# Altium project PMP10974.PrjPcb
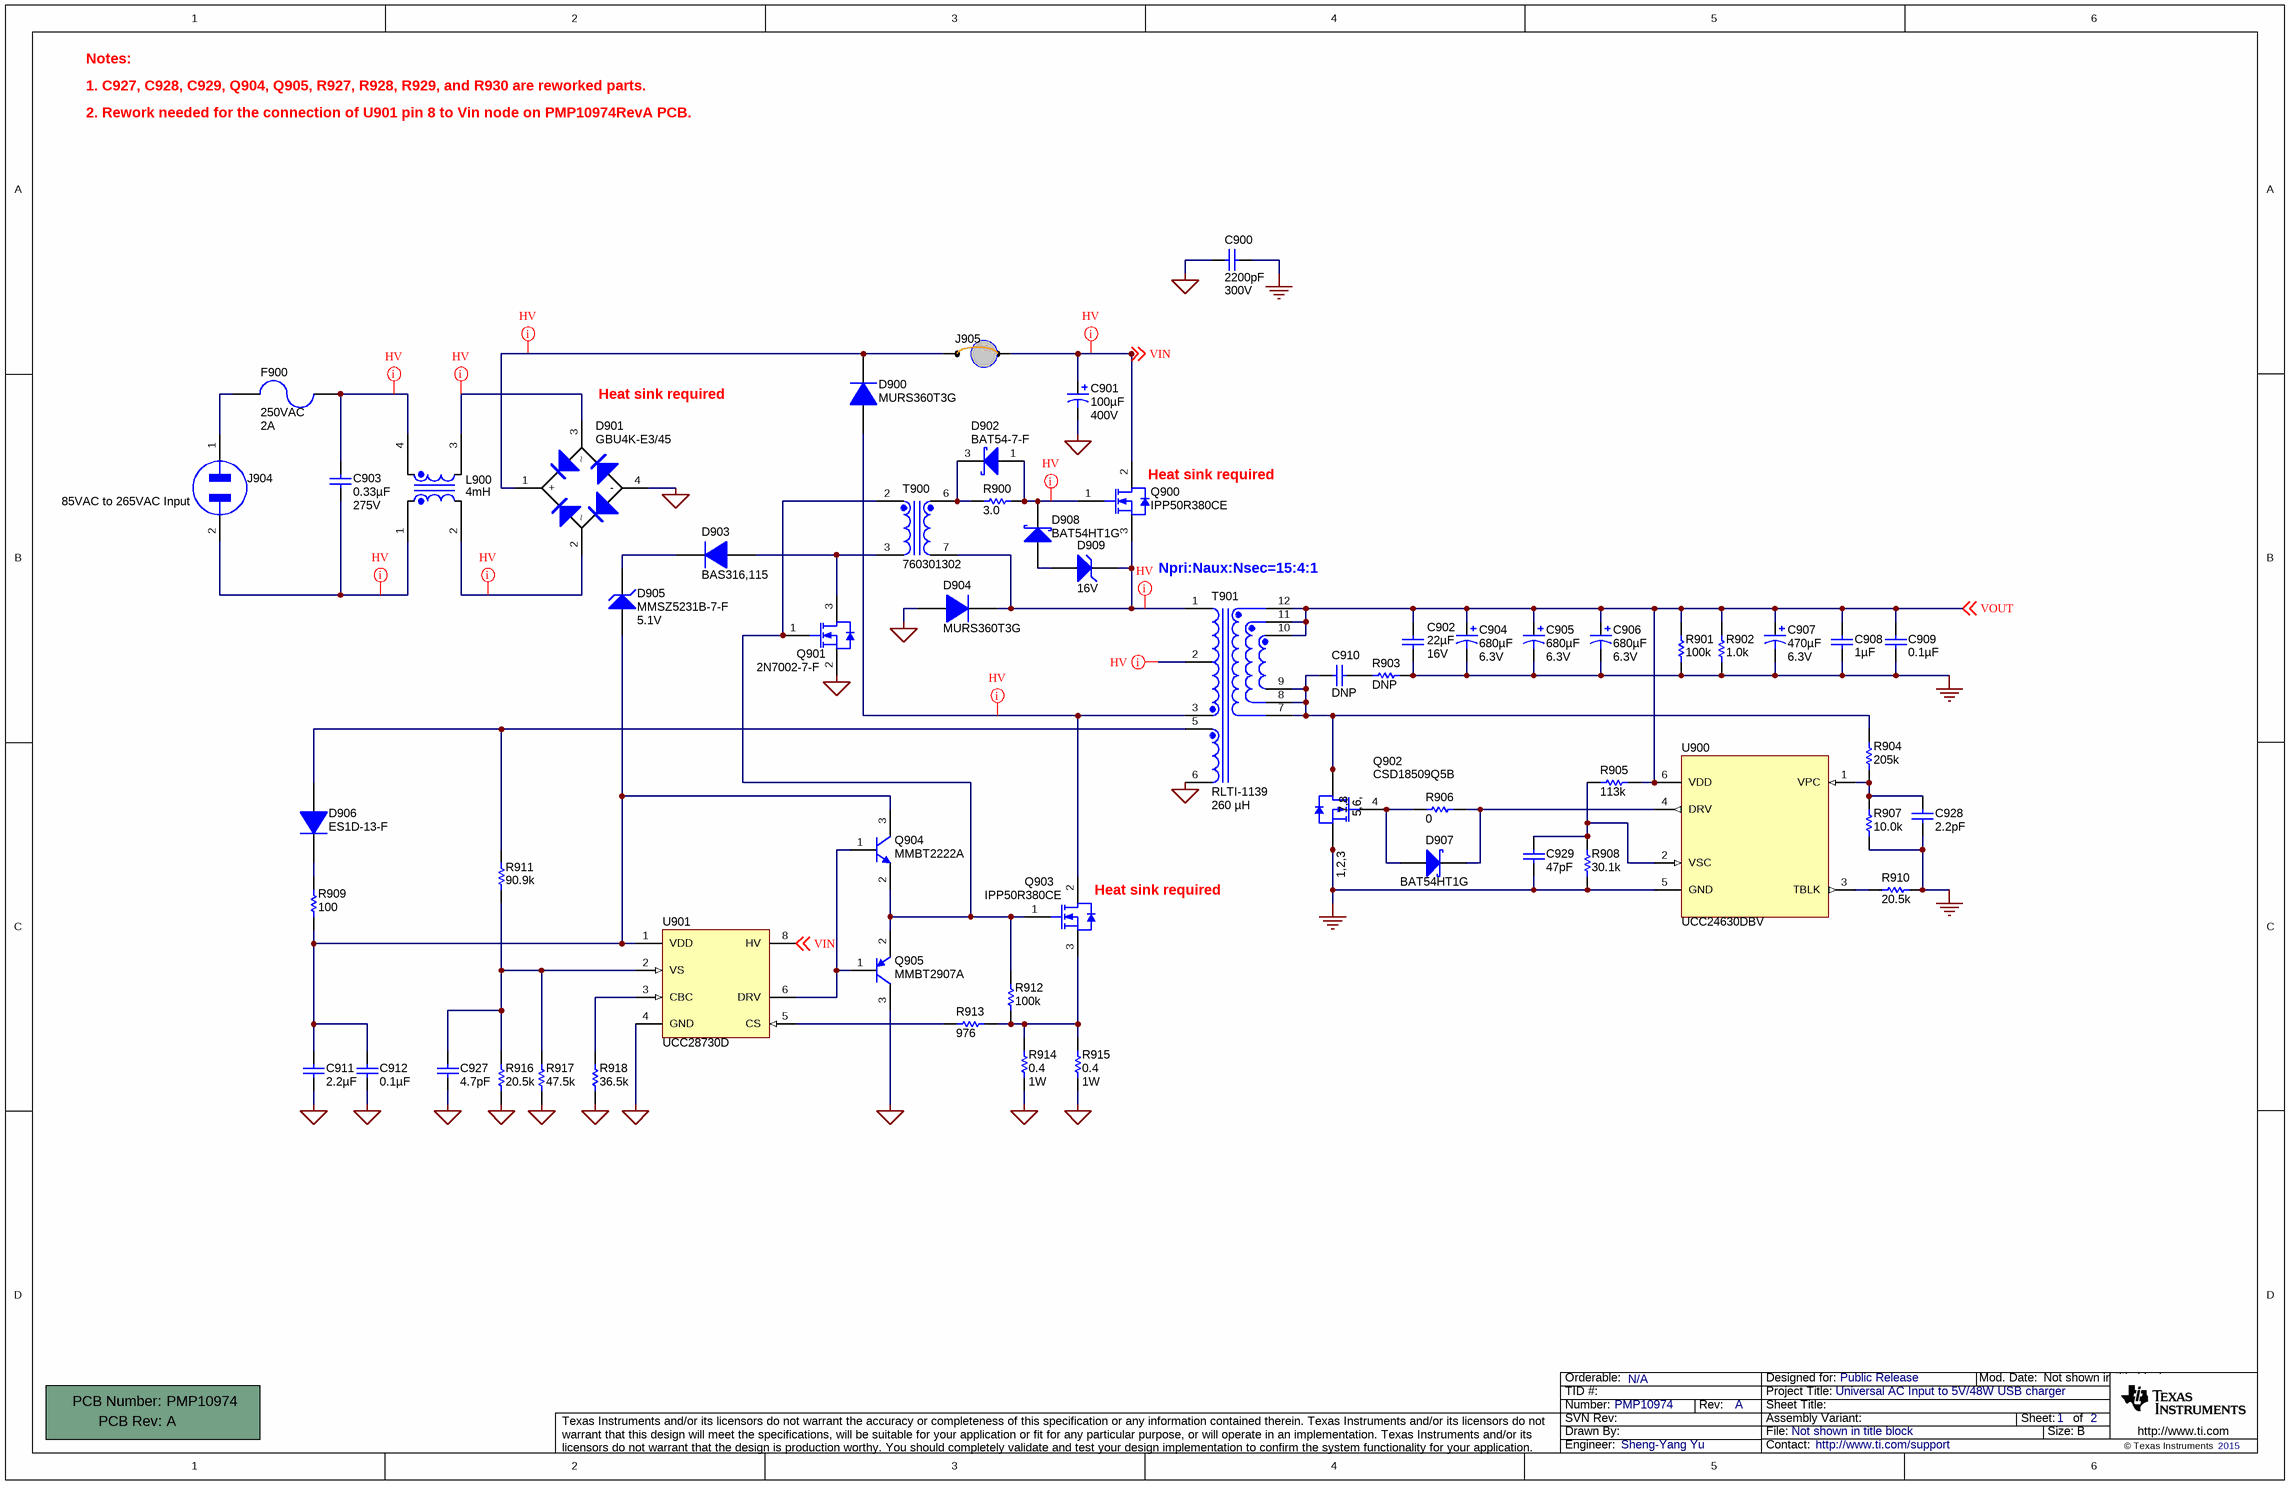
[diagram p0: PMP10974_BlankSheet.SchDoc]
CopyrightYear: 2015; EVM_Orderable: N/A; PCB_Layout: Sheng-Yang Yu; PCB_Rev: A; PRJ_Customer: Public Release; PRJ_Engineer: Sheng-Yang Yu; PRJ_Number: PMP10974; PRJ_Title: Universal AC Input to 5V/48W USB charger; SCH_Rev: A; TechSupport: http://www.ti.com/support
2 sheets, 100 parts. Net scope: global (net labels, ports and power ports of the same name join across sheets).
Board file: PMP10974_TID.PcbDoc
Sheets:
  PMP10974_BlankSheet.SchDoc
  PMP10974_TID_Hardware.SchDoc

## Sheet PMP10974_BlankSheet.SchDoc
size 431 x 279 mm; Date: Not shown in title block; ApprovedBy: Not shown in title block; CheckedBy: Not shown in title block; Author: Not shown in title block; CompanyName: Not shown in title block; Engineer: Not shown in title block; Organization: Not shown in title block; Address1: Not shown in title block; Address2: Not shown in title block; Address3: Not shown in title block; Address4: Not shown in title block; DocumentNumber: 1; Revision: Use project parameter SCH_Rev; SheetNumber: 1; SheetTotal: 2; PageSetup: Record=PageOptions¦CenterHorizontal=True¦CenterVertical=True¦PrintScale=1.00¦XCorrection=1.00¦YCorrection=1.00¦PrintKind=0¦BorderSize=5000000¦LeftOffset=0¦BottomOffset=0¦Orientation=2¦PaperLength=1000¦PaperWidth=1000¦Scale=100¦PaperSource=15¦PrintQuality=600¦MediaType=1¦DitherType=10¦PaperKind=Letter¦PrintScaleMode=1

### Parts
!PCB900  Printed Circuit Board  (value not drawn)  (mechanical)
C900  ValueDisplayed: 2200pF  Value2: 300V  [E_900x700x900]  (hidden comment: DE6E3KJ222MN3A)
C901  ValueDisplayed: 100µF  Value2: 400V  [CAPPR7.5-18X25]  (hidden comment: UPT2G101MHD6)
C902  ValueDisplayed: 22µF  Value2: 16V  [1206]  (hidden comment: 1206YD226MAT2A)
C903  ValueDisplayed: 0.33µF  Value2: 275V  [ECQUG_1500x800x1500]  (hidden comment: 890324024003)
C904  ValueDisplayed: 680µF  Value2: 6.3V  [CAPPRD500W60D1000H1250]  (hidden comment: PLE0J681MDO1)
C905  ValueDisplayed: 680µF  Value2: 6.3V  [CAPPRD500W60D1000H1250]  (hidden comment: PLE0J681MDO1)
C906  ValueDisplayed: 680µF  Value2: 6.3V  [CAPPRD500W60D1000H1250]  (hidden comment: PLE0J681MDO1)
C907  ValueDisplayed: 470µF  Value2: 6.3V  [SEPC_C55]  (hidden comment: 6.3YXJ470M6.3X11)
C908  ValueDisplayed: 1µF  [0603]  (hidden comment: C0603C105K4PACTU)
C909  ValueDisplayed: 0.1µF  [0805_HV]  (hidden comment: 08053C104KAT2A)
C910  ValueDisplayed: DNP  [0603]  (hidden comment: C1608C0G2A101J)
C911  ValueDisplayed: 2.2µF  [1206]  (hidden comment: GRM316R61E225KA12D)
C912  ValueDisplayed: 0.1µF  [0603]  (hidden comment: 06035C104KAT2A)
C927  ValueDisplayed: 4.7pF  [0603]  (hidden comment: 06035A4R7CAT2A)
C928  ValueDisplayed: 2.2pF  [0603]  (hidden comment: 06035A2R2CAT2A)
C929  ValueDisplayed: 47pF  [0603]  (hidden comment: 06035A470JAT2A)
D900  MURS360T3G  [SMC]
D901  GBU4K-E3/45  [GBU]
D902  BAT54-7-F  [SOT-23]
D903  BAS316,115  [sod-323]
D904  MURS360T3G  [SMC]
D905  MMSZ5231B-7-F  value 5.1V  [SOD-123]
D906  ES1D-13-F  [SMA]
D907  BAT54HT1G  [sod-323]
D908  BAT54HT1G  [sod-323]
D909  value 16V  [sod-323]  (hidden comment: MMSZ5246BS-7-F)
F900  VAC_V: 250VAC  Irating_A: 2A  [Fuse_RST]  (hidden comment: RST 2-BULK)
J904  770W-X2/10  [CONN_AC_770W-SERIES]  (value not drawn)
J905  923345-03-C  [923345-03-C]  (value not drawn)
L900  ValueDisplayed: 4mH  [WE-CMB_XS]  (hidden comment: 744821240)
Q900  IPP50R380CE  [TO-220AB]
Q901  2N7002-7-F  [SOT-23]
Q902  CSD18509Q5B  [TRANS_NexFET_Q5B]
Q903  IPP50R380CE  [TO-220AB]
Q904  MMBT2222A  [SOT-23]
Q905  MMBT2907A  [SOT-23]
R900  ValueDisplayed: 3.0  [0603]  (hidden comment: CRCW06033R00JNEA)
R901  ValueDisplayed: 100k  [0603]  (hidden comment: CRCW0603100KJNEA)
R902  ValueDisplayed: 1.0k  [0603]  (hidden comment: CRCW06031K00JNEA)
R903  value DNP  [0805_HV]  (hidden comment: CRCW08050000Z0EA)
R904  ValueDisplayed: 205k  [0603]  (hidden comment: CRCW0603205KFKEA)
R905  ValueDisplayed: 113k  [0603]  (hidden comment: CRCW0603113KFKEA)
R906  ValueDisplayed: 0  [0603]  (hidden comment: CRCW06030000Z0EA)
R907  ValueDisplayed: 10.0k  [0603]  (hidden comment: CRCW060310K0FKEA)
R908  ValueDisplayed: 30.1k  [0603]  (hidden comment: CRCW060330K1FKEA)
R909  ValueDisplayed: 100  [0603]  (hidden comment: CRCW0603100RFKEA)
R910  ValueDisplayed: 20.5k  [0603]  (hidden comment: CRCW060320K5FKEA)
R911  ValueDisplayed: 90.9k  [0603]  (hidden comment: CRCW060390K9FKEA)
R912  value 100k  [0805_HV]  (hidden comment: CRCW0805100KJNEA)
R913  ValueDisplayed: 976  [0603]  (hidden comment: CRCW0603976RFKEA)
R914  ValueDisplayed: 0.4  Value2: 1W  [2010]  (hidden comment: CSRN2010FKR400)
R915  ValueDisplayed: 0.4  Value2: 1W  [2010]  (hidden comment: CSRN2010FKR400)
R916  ValueDisplayed: 20.5k  [0603]  (hidden comment: CRCW060320K5FKEA)
R917  ValueDisplayed: 47.5k  [0603]  (hidden comment: CRCW060347K5FKEA)
R918  ValueDisplayed: 36.5k  [0603]  (hidden comment: CRCW060336K5FKEA)
T900  760301302  [Wurth_760301302]
T901  RLTI-1139  value 260 µH  [Renco_RLTI-1132]
U900  UCC24630DBV  [DBV0006A_N]
U901  UCC28730D  [D0007A_N]

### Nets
GND: C900.2 C901.2(-) C911.2 C912.2 C927.2 D901.4(-) D904.2(A) Q901.2(S) Q905.3(C) R914.1 R915.1 R916.1 R917.1 R918.1 T901.6 U901.4(GND)
GND2: C900.1 C902.2 C904.2(-) C905.2(-) C906.2(-) C907.2(-) C908.2 C909.2 C928.2 C929.2 Q902.1(S) Q902.2(S) Q902.3(S) R901.1 R902.1 R903.2 R907.1 R908.1 R910.1 U900.5(GND)
VIN: C901.1(+) J905.2 Q900.2(D) U901.8(HV) ; off-sheet VIN
VOUT: C902.1 C904.1(+) C905.1(+) C906.1(+) C907.1(+) C908.1 C909.1 R901.2 R902.2 R905.2 T901.10(5V) T901.11(5V) T901.12(5V) U900.6(VDD) ; off-sheet VOUT
NetC903_1: C903.1 F900.1 L900.4
NetC903_2: C903.2 J904.2(Hot) L900.1
NetC910_1: C910.1 R903.1
NetC910_2: C910.2 Q902.5(D) Q902.6(D) Q902.7(D) Q902.8(D) R904.2 T901.7(RET) T901.8(RET) T901.9(RET)
NetC911_1: C911.1 C912.1 D905.2(A) Q904.3(C) R909.1 U901.1(VDD)
NetC927_1: C927.1 R911.1 R916.2 R917.2 U901.2(VS)
NetC928_1: C928.1 R904.1 R907.2 U900.1(VPC)
NetC929_1: C929.1 R905.1 R908.2 U900.2(VSC)
NetD900_1: D900.1(K) D901.1(+) J905.1
NetD900_2: D900.2(A) Q903.2(D) T901.3(DRAIN)
NetD901_2: D901.2 L900.2
NetD901_3: D901.3 L900.3
NetD902_1: D902.1(A) D908.1(K) Q900.1(G) R900.2
NetD902_3: D902.3(K) R900.1 T900.6
NetD903_1: D903.1(K) D905.1(K)
NetD903_2: D903.2(A) Q901.3(D) T900.3
NetD904_1: D904.1(K) D909.1(K) Q900.3(S) T900.7 T901.1(VDC+)
NetD906_1: D906.1(K) R909.2
NetD906_2: D906.2(A) R911.2 T901.5
NetD907_1: D907.1(K) R906.2 U900.4(DRV)
NetD907_2: D907.2(A) Q902.4(G) R906.1
NetD908_2: D908.2(A) D909.2(A)
NetF900_2: F900.2 J904.1(Neutral)
NetQ901_1: Q901.1(G) Q903.1(G) Q904.2(E) Q905.2(E) R912.2 T900.2
NetQ903_3: Q903.3(S) R912.1 R913.2 R914.2 R915.2
NetQ904_1: Q904.1(B) Q905.1(B) U901.6(DRV)
NetR910_2: R910.2 U900.3(TBLK)
NetR913_1: R913.1 U901.5(CS)
NetR918_2: R918.2 U901.3(CBC)

Not connected (* = marked no-connect by the designer): T901 2

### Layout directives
net class HV: NetC903_1, NetC903_2, NetD900_1, NetD900_2, NetD901_2, NetD901_3, NetD902_1, NetD904_1, NetT901_2, VIN

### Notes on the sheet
- Notes:
- 1. C927, C928, C929, Q904, Q905, R927, R928, R929, and R930 are reworked parts.
- 2. Rework needed for the connection of U901 pin 8 to Vin node on PMP10974RevA PCB.
- (near D901) Heat sink required
- (near J904) 85VAC to 265VAC Input
- (near Q900) Heat sink required
- (near T901) Npri:Naux:Nsec=15:4:1
- (near Q903) Heat sink required

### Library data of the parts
!PCB900 = PCB: Manufacturer: Any; PartNumber: PMP10974; SymbolCreator: a0412235
C900 = DE6E3KJ222MN3A: CAP, CERM, 2200 pF, 300 V, +/- 20%, E, TH, 2- Leads, Body 9x7mm, Pin Spacing 7.5mm; Manufacturer: MuRata; Polarized: N; CompType: Capacitor; Value: 2200pF; U/M: EA; Cap_F: 0.0000000022; Tolerance_%: 20; Value1: Unknown; VDC_V: 300; TaMin_C: -40; TaMax_C: 125; Cap_Case: 9x7x9mm
C901 = EEUED2W330S: CAP ALUM 100UF 400V 20% RADIAL; Manufacturer: Panasonic; Polarized: Y; CompType: Capacitor; U/M: EA; Cap_F: 0.000033; Tolerance_%: 20; Value1: 0.868117 ohm; VDC_V: 450; ESR_ohm: 0.868117; IRMS_A: 0.85; TaMin_C: -25; TaMax_C: 105; AC_Derating: 0.3
C902 = 1206YD226MAT2A: CAP, CERM, 22 µF, 16 V, +/- 20%, X5R, 1206; Manufacturer: AVX; Polarized: N; CompType: Capacitor; Value: 22uF; U/M: EA; Cap_F: 0.000022; Tolerance_%: 20; Value1: Unknown; VDC_V: 16; TaMin_C: -55; TaMax_C: 85
C903 = ECQ-U3A104MG: CAP FILM 0.33UF 10% 275V RADIAL; Manufacturer: Wurth; Polarized: N; CompType: Capacitor; U/M: EA; Cap_F: 0.0000001; Tolerance_%: 20; Value1: Unknown; VDC_V: 275; TaMin_C: -40; TaMax_C: 100; Cap_Case: 15x8x15mm
C904-C906 = UVY2G4R7MPD: CAP ALUM 680UF 6.3V 20% RADIAL; Manufacturer: Nichicon; Polarized: Y; CompType: Capacitor; U/M: EA; Cap_F: 0.0000047; Tolerance_%: 20; Value1: Unknown; VDC_V: 6.3; TaMin_C: -40; TaMax_C: 105; Cap_Case: 10x12.5
C907 = 6SEPC220M: CAP ALUM 470UF 6.3V 20% RADIAL; Manufacturer: Rubycon; Polarized: Y; CompType: Capacitor; U/M: EA; Cap_F: 0.00022; Tolerance_%: 20; Value1: 0.018 ohm; VDC_V: 6.3; ESR_ohm: 0.018; IRMS_A: 2.98; TaMin_C: -55; TaMax_C: 105; Cap_Case: 6.3x5.5
C908 = C0603C105K4PACTU: CAP, CERM, 1 µF, 16 V, +/- 10%, X5R, 0603; Manufacturer: Kemet; Polarized: N; CompType: Capacitor; Value: 1uF; U/M: EA; Cap_F: 0.000001; Tolerance_%: 10; Value1: Unknown; VDC_V: 16; Value2: 16V; TaMin_C: -55; TaMax_C: 85
C909 = 08053C104KAT2A: CAP, CERM, 0.1uF, 25V, +/-10%, X7R, 0805; Manufacturer: AVX; Polarized: N; CompType: Capacitor; U/M: EA; Cap_F: 0.0000001; Tolerance_%: 10; ESR_Ohm: 0.28; Value1: 0.28 ohm; VDC_V: 25; TaMin_C: -55; TaMax_C: 125; Cap_Case: 0805
C910 = C1608C0G2A101J: CAP, CERM, 100pF, 100V, +/-5%, C0G/NP0, 0603; Manufacturer: TDK; Polarized: N; CompType: Capacitor; U/M: EA; Cap_F: 0.0000000001; Tolerance_%: 5; ESR_Ohm: 0.1202; Value1: 0.1202 ohm; VDC_V: 100; TaMin_C: -55; TaMax_C: 125
C911 = GRM316R61E225KA12D: CAP, CERM, 2.2 µF, 25 V, +/- 10%, X5R, 1206; Manufacturer: MuRata; Polarized: N; CompType: Capacitor; Value: 2.2uF; U/M: EA; Cap_F: 0.0000022; Tolerance_%: 10; ESR_ohm: 0.006; Value1: 0.006 ohm; VDC_V: 25; Value2: 25V; TaMin_C: -55; TaMax_C: 85
C912 = 06035C104KAT2A: CAP, CERM, 0.1uF, 50V, +/-10%, X7R, 0603; Manufacturer: AVX; Polarized: N; CompType: Capacitor; U/M: EA; Cap_F: 0.0000001; Tolerance_%: 10; Value1: Unknown; VDC_V: 50; TaMin_C: -55; TaMax_C: 125
C927 = 06035A4R7CAT2A: CAP, CERM, 4.7 pF, 50 V, +/- 5%, C0G/NP0, 0603; Manufacturer: AVX; Polarized: N; CompType: Capacitor; Value: 4.7pF; U/M: EA; Cap_F: 0.0000000000047; Tolerance_%: 5; ESR_ohm: 0.633; Value1: 0.633 ohm; VDC_V: 50; Value2: 50V; TaMin_C: -55; TaMax_C: 125
C928 = 06035A2R2CAT2A: CAP, CERM, 2.2 pF, 50 V, +/- 11%, C0G/NP0, 0603; Manufacturer: AVX; Polarized: N; CompType: Capacitor; Value: 2.2pF; U/M: EA; Cap_F: 0.0000000000022; Tolerance_%: 11; ESR_ohm: 1.033; Value1: 1.033 ohm; VDC_V: 50; Value2: 50V; TaMin_C: -55; TaMax_C: 125
C929 = 06035A470JAT2A: CAP, CERM, 47 pF, 50 V, +/- 5%, C0G/NP0, 0603; Manufacturer: AVX; Polarized: N; CompType: Capacitor; Value: 47pF; U/M: EA; Cap_F: 0.000000000047; Tolerance_%: 5; ESR_ohm: 0.174; Value1: 0.174 ohm; VDC_V: 50; Value2: 50V; TaMin_C: -55; TaMax_C: 125
D900 D904 = MURS360T3G: Diode, Ultrafast, 600 V, 3 A, SMC; Manufacturer: ON Semiconductor; U/M: EA; Vf_V: 1.25; Value: 600V; Value1: 3A; Value2: 1.25V; Io_A: 3; Vr_V: 600; TJmax_C: 175; RJC_CperW: 11
D901 = GBU4K-E3/45: Diode, Switching-Bridge, 800V, 4A, TH; Manufacturer: Vishay-Semiconductor; U/M: EA; Vf_V: 1; Value2: 1V; Io_A: 4; Vr_V: 800; TJmax_C: 150; RJC_CperW: 4.2
D902 = BAT54-7-F: Diode, Schottky, 30 V, 0.2 A, SOT-23; Manufacturer: Diodes Inc.; U/M: EA; Vf_V: 0.65; Value: 30V; Value1: 0.2A; Value2: 0.65V; Io_A: 0.2; Vr_V: 30; TJmax_C: 125
D903 = BAS316,115: Diode, Ultrafast, 100 V, 0.25 A, SOD-323; Manufacturer: NXP Semiconductor; U/M: EA; Vf_V: 1.4; Value: 100V; Value1: 0.25A; Value2: 1.4V; Io_A: 0.25; Vr_V: 100; TJmax_C: 150
D905 = MMSZ5231B-7-F: Diode, Zener, 5.1 V, 500 mW, SOD-123; Manufacturer: Diodes Inc.; SymbolCreator: a0412235; U/M: EA; Power_W: 0.5; Vz_V: 5.1; Value1: 0.5W; RJA_CperW: 350
D906 = ES1D-13-F: Diode, Ultrafast, 200V, 1A, SMA; Manufacturer: Diodes Inc.; U/M: EA; Vf_V: 0.92; Value2: 0.92V; Io_A: 1; Vr_V: 200; TJmax_C: 150; RJC_CperW: 25
D907 D908 = BAT54HT1G: Diode, Schottky, 30V, 0.2A, SOD-323; Manufacturer: ON Semiconductor; U/M: EA; Vf_V: 0.35; Value2: 0.35V; Io_A: 0.2; Vr_V: 30
D909 = MMSZ5246BS-7-F: Diode, Zener, 16 V, 200 mW, SOD-323; Manufacturer: Diodes Inc.; SymbolCreator: a0412235; U/M: EA; Power_W: 0.2; Vz_V: 16; Value1: 0.2W; RJA_CperW: 350
F900 = RST 500: FUSE BOARD MOUNT 2A 250VAC RAD; Manufacturer: Bel Fuse; U/M: EA; OpeningTime_100%_min: 1; OpeningTime_200%_max: 120; VDC_V: 250; Rtyp_Ohm: 0.18; MeltingTyp: 1.7; Vdrop: 0.114; Soldering_Wave_MaxTemp_C: 260; Soldering_Wave_MaxTime_s: 10
J904 = 770W-X2/10: AC Receptacle, 2.5A, R/A, TH; Manufacturer: Qualtek Electronics Corporation; SymbolCreator: a0412235; U/M: EA
J905 = 923345-03-C: Jumper Wire, 300mil spacing, Orange, pkg of 200; Manufacturer: 3M; SymbolCreator: a0412235; U/M: EA
L900 = 744821240: Coupled inductor, 4 mH, 1.5 A, 0.14 ohm, +/- 30%, TH; Manufacturer: Wurth Elektronik eiSos; SymbolCreator: a0412235; Ind_H: 4.0E-3; DCR_ohm: 0.14; Isat: 1.5; Tolerance_%: 30; Value: 4mH
Q900 Q903 = IPP50R199CP: MOSFET N CH 500V 9.9A PGTO220; Manufacturer: Infineon Technologies; Alternate Manufacturer: None; U/M: EA; Value: 550V; VdsMax_V: 550; Value1: ? ohm; Rdson45_ohm: 0; Value2: 34 nC; QgTyp_nC: 34; Vgs_V: 20
Q901 = 2N7002-7-F: MOSFET, N-CH, 60 V, 0.17 A, SOT-23; Manufacturer: Diodes Inc.; Alternate Manufacturer: None; U/M: EA; ChType: N; Value: 60V; VdsMax_V: 60; Value1: 7.5 ohm; Rdson45_ohm: 7.5; Value2: 223 nC; QgTyp_nC: 223; Vgs_V: 20; IdsMax_A: 0.17
Q902 = CSD18509Q5B: MOSFET, N-CH, 40 V, 38 A, SON 5x6mm; Manufacturer: Texas Instruments; Alternate Manufacturer: None; U/M: EA; ChType: N; Value: 40V; VdsMax_V: 40; Value1: 0.0017 ohm; Rdson45_ohm: 0.0017; Value2: 150 nC; QgTyp_nC: 150; Vgs_V: 20; IdsMax_A: 38
Q904 = MMBT2222A, Fairchild Semiconductor: Transistor, NPN, 40 V, 0.15 A, SOT-23; CompType: BJT; PNP: 0; NPN: 1; Vceo_V: 40; Vcesat1_V: 0.3; Value: 40 V; IcRated_A: 0.15; Value1: 0.15 A; HfeMax: 300; TaMin_C: -55; TaMax_C: 150; U/M: EA
Q905 = MMBT2907A, Fairchild Semiconductor: Transistor, PNP, 60 V, 0.8 A, SOT-23; CompType: BJT; PNP: 1; NPN: 0; Vceo_V: 60; Vcesat1_V: 1.6; Value: 60 V; IcRated_A: 0.8; Value1: 0.8 A; HfeMax: 300; TaMin_C: -55; TaMax_C: 150; U/M: EA
R900 = CRCW06033R00JNEA: RES, 3.0, 5%, 0.1 W, 0603; Manufacturer: Vishay-Dale; CompType: Resistor; Value: 3.0; Res_ohm: 3; Value_Code: 3R00; Tolerance_%: 5; Power_W: 0.1; Value2: 0.1W; VDC_V: 75; TempCo: 200 ppm/C; EIA_Code: E24; U/M: EA
R901 = CRCW0603100KJNEA: RES, 100 k, 5%, 0.1 W, 0603; Manufacturer: Vishay-Dale; CompType: Resistor; Value: 100k; Res_ohm: 100000; Tolerance_%: 5; Power_W: 0.1; Value2: 0.1W; VDC_V: 75; TempCo: 200 ppm/C; EIA_Code: E24; U/M: EA
R902 = CRCW06031K00JNEA: RES, 1.0 k, 5%, 0.1 W, 0603; Manufacturer: Vishay-Dale; CompType: Resistor; Value: 1.0k; Res_ohm: 1000; Value_Code: 1k00; Tolerance_%: 5; Power_W: 0.1; Value2: 0.1W; VDC_V: 75; TempCo: 200 ppm/C; EIA_Code: E24; U/M: EA
R903 = CRCW08050000Z0EA: RES, 0 ohm, 5%, 0.125W, 0805; Manufacturer: Vishay-Dale; CompType: Resistor; Res_ohm: 0; Value_Code: 0000; Tolerance_%: 5; Power_W: 0.125; VDC_V: 150; TempCo: 200 ppm/C; EIA_Code: E24; U/M: EA
R904 = CRCW0603205KFKEA: RES, 205 k, 1%, 0.1 W, 0603; Manufacturer: Vishay-Dale; CompType: Resistor; Value: 205k; Res_ohm: 205000; Tolerance_%: 1; Power_W: 0.1; Value2: 0.1W; VDC_V: 75; TempCo: 100 ppm/C; EIA_Code: E96; U/M: EA
R905 = CRCW0603113KFKEA: RES, 113 k, 1%, 0.1 W, 0603; Manufacturer: Vishay-Dale; CompType: Resistor; Value: 113k; Res_ohm: 113000; Tolerance_%: 1; Power_W: 0.1; Value2: 0.1W; VDC_V: 75; TempCo: 100 ppm/C; EIA_Code: E96; U/M: EA
R906 = CRCW06030000Z0EA: RES, 0, 5%, 0.1 W, 0603; Manufacturer: Vishay-Dale; CompType: Resistor; Value: 0; Value_Code: 0000; Tolerance_%: 5; Power_W: 0.1; Value2: 0.1W; VDC_V: 75; TempCo: 200 ppm/C; EIA_Code: E24; U/M: EA
R907 = CRCW060310K0FKEA: RES, 10.0 k, 1%, 0.1 W, 0603; Manufacturer: Vishay-Dale; CompType: Resistor; Value: 10.0k; Res_ohm: 10000; Value_Code: 10k0; Tolerance_%: 1; Power_W: 0.1; Value2: 0.1W; VDC_V: 75; TempCo: 100 ppm/C; EIA_Code: E96; U/M: EA
R908 = CRCW060330K1FKEA: RES, 30.1 k, 1%, 0.1 W, 0603; Manufacturer: Vishay-Dale; CompType: Resistor; Value: 30.1k; Res_ohm: 30100; Value_Code: 30k1; Tolerance_%: 1; Power_W: 0.1; Value2: 0.1W; VDC_V: 75; TempCo: 100 ppm/C; EIA_Code: E96; U/M: EA
R909 = CRCW0603100RFKEA: RES, 100, 1%, 0.1 W, 0603; Manufacturer: Vishay-Dale; CompType: Resistor; Value: 100; Value_Code: 100R; Tolerance_%: 1; Power_W: 0.1; Value2: 0.1W; VDC_V: 75; TempCo: 100 ppm/C; EIA_Code: E96; U/M: EA
R910 R916 = CRCW060320K5FKEA: RES, 20.5 k, 1%, 0.1 W, 0603; Manufacturer: Vishay-Dale; CompType: Resistor; Value: 20.5k; Res_ohm: 20500; Value_Code: 20k5; Tolerance_%: 1; Power_W: 0.1; Value2: 0.1W; VDC_V: 75; TempCo: 100 ppm/C; EIA_Code: E96; U/M: EA
R911 = CRCW060390K9FKEA: RES, 90.9 k, 1%, 0.1 W, 0603; Manufacturer: Vishay-Dale; CompType: Resistor; Value: 90.9k; Res_ohm: 90900; Value_Code: 90k9; Tolerance_%: 1; Power_W: 0.1; Value2: 0.1W; VDC_V: 75; TempCo: 100 ppm/C; EIA_Code: E96; U/M: EA
R912 = CRCW0805100KJNEA: RES, 100k ohm, 5%, 0.125W, 0805; Manufacturer: Vishay-Dale; CompType: Resistor; Res_ohm: 100000; Tolerance_%: 5; Power_W: 0.125; VDC_V: 150; TempCo: 200 ppm/C; EIA_Code: E24; U/M: EA
R913 = CRCW0603976RFKEA: RES, 976, 1%, 0.1 W, 0603; Manufacturer: Vishay-Dale; CompType: Resistor; Value: 976; Value_Code: 976R; Tolerance_%: 1; Power_W: 0.1; Value2: 0.1W; VDC_V: 75; TempCo: 100 ppm/C; EIA_Code: E96; U/M: EA
R914 R915 = CSRN2010FKR400: RES, 0.4, 1%, 1 W, 2010; Manufacturer: Stackpole Electronics Inc; CompType: Resistor; Value: 0.4; Value_Code: R400; Tolerance_%: 1; TempCo: 250 ppm/C; U/M: EA
R917 = CRCW060347K5FKEA: RES, 47.5 k, 1%, 0.1 W, 0603; Manufacturer: Vishay-Dale; CompType: Resistor; Value: 47.5k; Res_ohm: 47500; Value_Code: 47k5; Tolerance_%: 1; Power_W: 0.1; Value2: 0.1W; VDC_V: 75; TempCo: 100 ppm/C; EIA_Code: E96; U/M: EA
R918 = CRCW060336K5FKEA: RES, 36.5 k, 1%, 0.1 W, 0603; Manufacturer: Vishay-Dale; CompType: Resistor; Res_ohm: 36500; Value: 36.5k; Value_Code: 36k5; Tolerance_%: 1; Power_W: 0.1; Value2: 0.1W; VDC_V: 75; TempCo: 100 ppm/C; EIA_Code: E96; U/M: EA
T900 = 760301302: Transformer, 750 uH, TH; Manufacturer: Wurth Elektronik eiSos; SymbolCreator: Altium; DCR_Ohm: 1.1; Value: 750 uH; LeakageL: 4 uH; U/M: EA
T901 = RLTI-1132: Transformer, 90 uH, TH; Manufacturer: Renco Electronics; SymbolCreator: Altium; DCR_Ohm: 0.075; LeakageL: 4 uH; U/M: EA
U900 = UCC24630DBV: SYNCRONOUS RECTIFIER CONTROLLER WITH LOW POWER STANDBY, DBV0006A; Manufacturer: Texas Instruments; SymbolCreator: a0411947; CompType: IC; U/M: EA
U901 = UCC28730D: Constant-Voltage Constant-Current Flyback Controller With PSR and Wake-Up Monitoring, D0007A; Alternate Manufacturer: None; Manufacturer: Texas Instruments; SymbolCreator: x0208325; CompType: IC; U/M: EA

## Sheet PMP10974_TID_Hardware.SchDoc
size 431 x 279 mm; Date: Not shown in title block; ApprovedBy: Not shown in title block; CheckedBy: Not shown in title block; Author: Not shown in title block; CompanyName: Not shown in title block; Engineer: Not shown in title block; Organization: Not shown in title block; Address1: Not shown in title block; Address2: Not shown in title block; Address3: Not shown in title block; Address4: Not shown in title block; DocumentNumber: 2; Revision: Use project parameter SCH_Rev; SheetNumber: 2; SheetTotal: 2; PageSetup: Record=PageOptions¦CenterHorizontal=True¦CenterVertical=True¦PrintScale=1.00¦XCorrection=1.00¦YCorrection=1.00¦PrintKind=0¦BorderSize=5000000¦LeftOffset=0¦BottomOffset=0¦Orientation=2¦PaperLength=1000¦PaperWidth=1000¦Scale=100¦PaperSource=15¦PrintQuality=600¦MediaType=1¦DitherType=10¦PaperKind=Letter¦PrintScaleMode=1
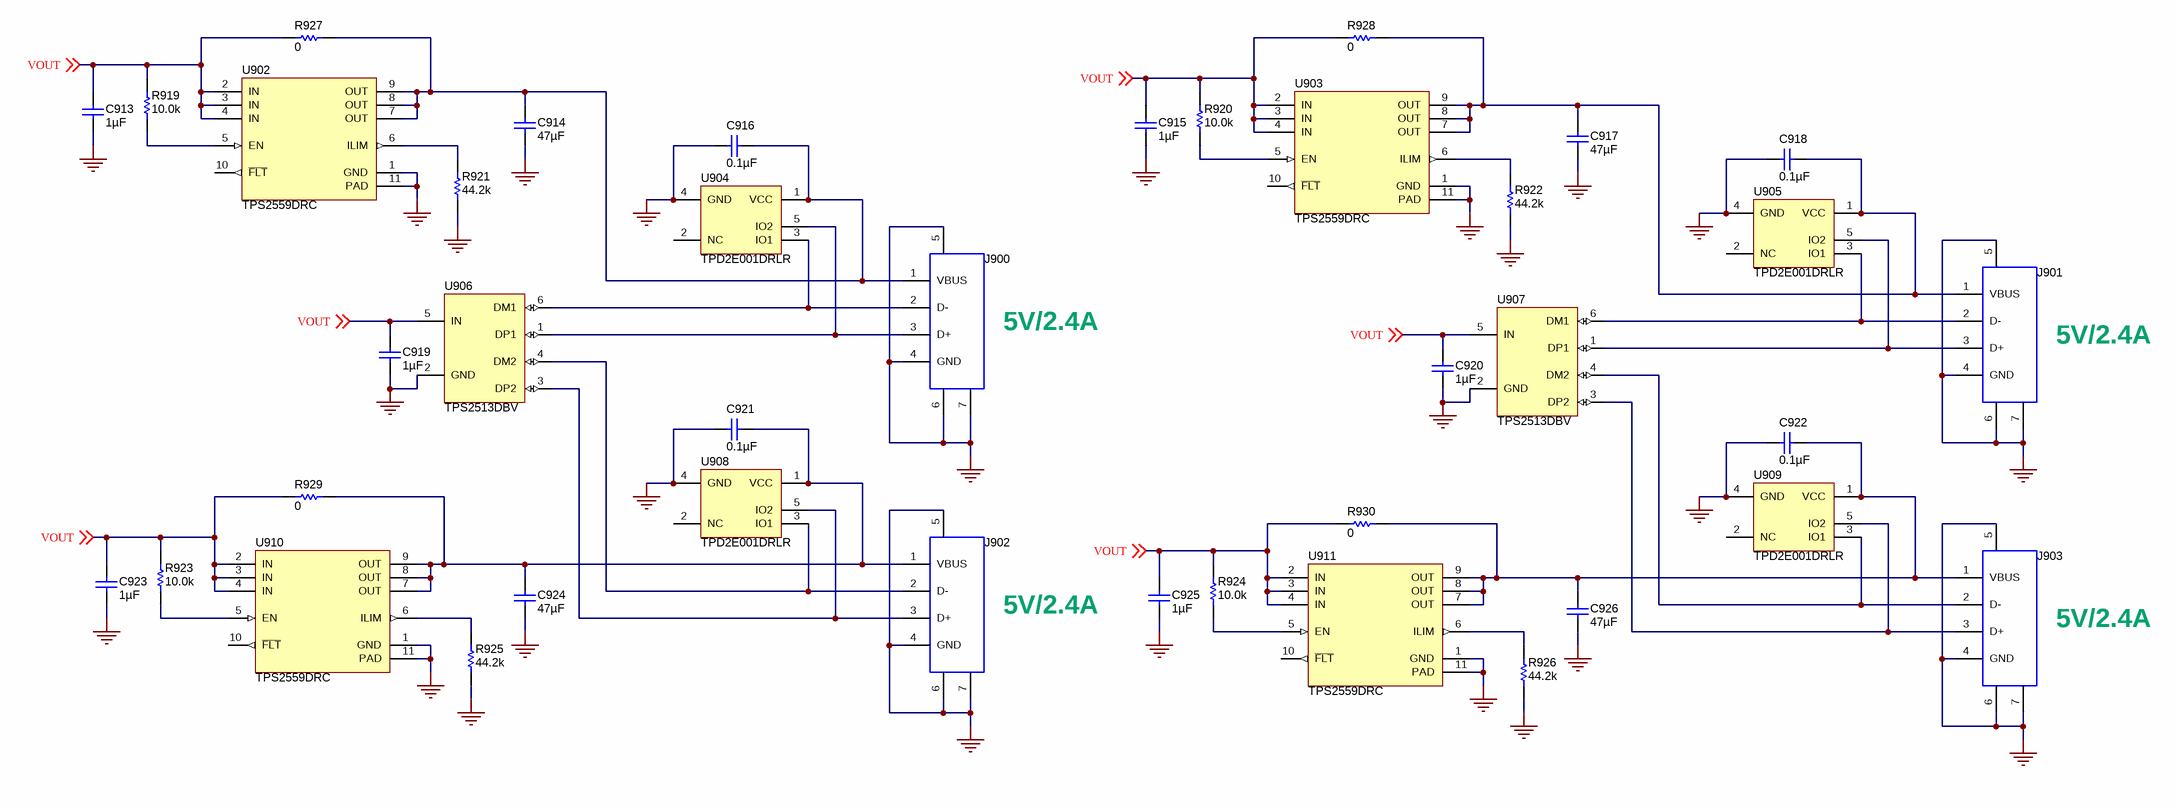
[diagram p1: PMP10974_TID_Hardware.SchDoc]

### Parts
C913  ValueDisplayed: 1µF  [0402L]  (hidden comment: GRM155R61A105KE15D)
C914  ValueDisplayed: 47µF  [1206L]  (hidden comment: GRM31CR61A476KE15L)
C915  ValueDisplayed: 1µF  [0402L]  (hidden comment: GRM155R61A105KE15D)
C916  ValueDisplayed: 0.1µF  [0402L]  (hidden comment: C1005X5R0J104K)
C917  ValueDisplayed: 47µF  [1206L]  (hidden comment: GRM31CR61A476KE15L)
C918  ValueDisplayed: 0.1µF  [0402L]  (hidden comment: C1005X5R0J104K)
C919  ValueDisplayed: 1µF  [0402L]  (hidden comment: GRM155R61A105KE15D)
C920  ValueDisplayed: 1µF  [0402L]  (hidden comment: GRM155R61A105KE15D)
C921  ValueDisplayed: 0.1µF  [0402L]  (hidden comment: C1005X5R0J104K)
C922  ValueDisplayed: 0.1µF  [0402L]  (hidden comment: C1005X5R0J104K)
C923  ValueDisplayed: 1µF  [0402L]  (hidden comment: GRM155R61A105KE15D)
C924  ValueDisplayed: 47µF  [1206L]  (hidden comment: GRM31CR61A476KE15L)
C925  ValueDisplayed: 1µF  [0402L]  (hidden comment: GRM155R61A105KE15D)
C926  ValueDisplayed: 47µF  [1206L]  (hidden comment: GRM31CR61A476KE15L)
J900  0894858000  [Molex_0894858000]  (value not drawn)
J901  0894858000  [Molex_0894858000]  (value not drawn)
J902  0894858000  [Molex_0894858000]  (value not drawn)
J903  0894858000  [Molex_0894858000]  (value not drawn)
R919  value 10.0k  [0402L]  (hidden comment: CRCW040210K0FKED)
R920  value 10.0k  [0402L]  (hidden comment: CRCW040210K0FKED)
R921  ValueDisplayed: 44.2k  [0402L]  (hidden comment: CRCW040244K2FKED)
R922  ValueDisplayed: 44.2k  [0402L]  (hidden comment: CRCW040244K2FKED)
R923  value 10.0k  [0402L]  (hidden comment: CRCW040210K0FKED)
R924  value 10.0k  [0402L]  (hidden comment: CRCW040210K0FKED)
R925  ValueDisplayed: 44.2k  [0402L]  (hidden comment: CRCW040244K2FKED)
R926  ValueDisplayed: 44.2k  [0402L]  (hidden comment: CRCW040244K2FKED)
R927  ValueDisplayed: 0  [1206]  (hidden comment: CRCW12060000Z0EA)
R928  ValueDisplayed: 0  [1206]  (hidden comment: CRCW12060000Z0EA)
R929  ValueDisplayed: 0  [1206]  (hidden comment: CRCW12060000Z0EA)
R930  ValueDisplayed: 0  [1206]  (hidden comment: CRCW12060000Z0EA)
U902  TPS2559DRC  [DRC0010A]
U903  TPS2559DRC  [DRC0010A]
U904  TPD2E001DRLR  [DRL0005A]
U905  TPD2E001DRLR  [DRL0005A]
U906  TPS2513DBV  [DBV0006A_L]
U907  TPS2513DBV  [DBV0006A_L]
U908  TPD2E001DRLR  [DRL0005A]
U909  TPD2E001DRLR  [DRL0005A]
U910  TPS2559DRC  [DRC0010A]
U911  TPS2559DRC  [DRC0010A]

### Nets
GND2: C913.2 C914.2 C915.2 C916.2 C917.2 C918.2 C919.2 C920.2 C921.2 C922.2 C923.2 C924.2 C925.2 C926.2 J900.4(GND) J900.5(Shield) J900.6(Shield) J900.7(Shield) J901.4(GND) J901.5(Shield) J901.6(Shield) J901.7(Shield) J902.4(GND) J902.5(Shield) J902.6(Shield) J902.7(Shield) J903.4(GND) J903.5(Shield) J903.6(Shield) J903.7(Shield) R921.1 R922.1 R925.1 R926.1 U902.1(GND) U902.11(PAD) U903.1(GND) U903.11(PAD) U904.4(GND) U905.4(GND) U906.2(GND) U907.2(GND) U908.4(GND) U909.4(GND) U910.1(GND) U910.11(PAD) U911.1(GND) U911.11(PAD)
VOUT: C913.1 C915.1 C919.1 C920.1 C923.1 C925.1 R919.2 R920.2 R923.2 R924.2 R927.1 R928.1 R929.1 R930.1 U902.2(IN) U902.3(IN) U902.4(IN) U903.2(IN) U903.3(IN) U903.4(IN) U906.5(IN) U907.5(IN) U910.2(IN) U910.3(IN) U910.4(IN) U911.2(IN) U911.3(IN) U911.4(IN) ; off-sheet VOUT
NetC914_1: C914.1 C916.1 J900.1(VBUS) R927.2 U902.7(OUT) U902.8(OUT) U902.9(OUT) U904.1(VCC)
NetC917_1: C917.1 C918.1 J901.1(VBUS) R928.2 U903.7(OUT) U903.8(OUT) U903.9(OUT) U905.1(VCC)
NetC921_1: C921.1 C924.1 J902.1(VBUS) R929.2 U908.1(VCC) U910.7(OUT) U910.8(OUT) U910.9(OUT)
NetC922_1: C922.1 C926.1 J903.1(VBUS) R930.2 U909.1(VCC) U911.7(OUT) U911.8(OUT) U911.9(OUT)
NetJ900_2: J900.2(D-) U904.3(IO1) U906.6(DM1)
NetJ900_3: J900.3(D+) U904.5(IO2) U906.1(DP1)
NetJ901_2: J901.2(D-) U905.3(IO1) U907.6(DM1)
NetJ901_3: J901.3(D+) U905.5(IO2) U907.1(DP1)
NetJ902_2: J902.2(D-) U906.4(DM2) U908.3(IO1)
NetJ902_3: J902.3(D+) U906.3(DP2) U908.5(IO2)
NetJ903_2: J903.2(D-) U907.4(DM2) U909.3(IO1)
NetJ903_3: J903.3(D+) U907.3(DP2) U909.5(IO2)
NetR919_1: R919.1 U902.5(EN)
NetR920_1: R920.1 U903.5(EN)
NetR921_2: R921.2 U902.6(ILIM)
NetR922_2: R922.2 U903.6(ILIM)
NetR923_1: R923.1 U910.5(EN)
NetR924_1: R924.1 U911.5(EN)
NetR925_2: R925.2 U910.6(ILIM)
NetR926_2: R926.2 U911.6(ILIM)

Not connected (* = marked no-connect by the designer): U902 10(~{FLT}); U903 10(~{FLT}); U904 2(NC); U905 2(NC); U908 2(NC); U909 2(NC); U910 10(~{FLT}); U911 10(~{FLT})

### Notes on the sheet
- (near J900) 5V/2.4A
- (near J901) 5V/2.4A
- (near J902) 5V/2.4A
- (near J903) 5V/2.4A

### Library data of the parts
C913 C915 C919 C920 C923 C925 = GRM155R61A105KE15D: CAP, CERM, 1uF, 10V, +/-10%, X5R, 0402; Manufacturer: MuRata; Polarized: N; CompType: Capacitor; U/M: EA; Cap_F: 0.000001; Tolerance_%: 10; Value1: Unknown; TaMin_C: -55; TaMax_C: 85; Cap_Case: 0402
C914 C917 C924 C926 = GRM31CR61A476KE15L: CAP, CERM, 47uF, 10V, +/-10%, X5R, 1206; Manufacturer: MuRata; Polarized: N; CompType: Capacitor; U/M: EA; Cap_F: 0.000047; Tolerance_%: 10; Value1: Unknown; TaMin_C: -55; TaMax_C: 85; Cap_Case: 1206
C916 C918 C921 C922 = C1005X5R0J104K: CAP, CERM, 0.1uF, 6.3V, +/-10%, X5R, 0402; Manufacturer: TDK; Polarized: N; CompType: Capacitor; U/M: EA; Cap_F: 0.0000001; Tolerance_%: 10; ESR_Ohm: 0.0186; Value1: 0.0186 ohm; VDC_V: 6.3; TaMin_C: -55; TaMax_C: 85; Cap_Case: 0402
J900-J903 = 0894858000: Connector, Shielded USB Type A, Gold, R/A, TH; Manufacturer: Molex; SymbolCreator: Altium; CompType: Receptacle; U/M: EA
R919 R920 R923 R924 = CRCW040210K0FKED: RES, 10.0k ohm, 1%, 0.063W, 0402; Manufacturer: Vishay-Dale; CompType: Resistor; Res_ohm: 10000; Value_Code: 10k0; Tolerance_%: 1; Power_W: 0.063; VDC_V: 50; TempCo: 100 ppm/C; EIA_Code: E96; U/M: EA
R921 R922 R925 R926 = CRCW040244K2FKED: RES, 44.2 k, 1%, 0.063 W, 0402; Manufacturer: Vishay-Dale; CompType: Resistor; Value: 44.2k; Res_ohm: 44200; Value_Code: 44k2; Tolerance_%: 1; Power_W: 0.063; Value2: 0.063W; VDC_V: 50; TempCo: 100 ppm/C; EIA_Code: E96; U/M: EA
R927-R930 = CRCW12060000Z0EA: RES, 0, 5%, 0.25 W, 1206; Manufacturer: Vishay-Dale; CompType: Resistor; Value: 0; Value_Code: 0000; Tolerance_%: 5; Power_W: 0.25; Value2: 0.25W; VDC_V: 200; TempCo: 200 ppm/C; EIA_Code: E24; U/M: EA
U902 U903 U910 U911 = TPS2559DRC: Precision Adjustable Current-Limited Power-Distribution Switch, DRC0010A; Manufacturer: Texas Instruments; SymbolCreator: a0799628; CompType: IC; U/M: EA
U904 U905 U908 U909 = TPD2E001DRLR: Low-Capacitance + / - 15 kV ESD-Protection Array for High-Speed Data Interfaces, 2 Channels, -40 to +85 degC, 5-pin SOT (DRL), Green (RoHS & no Sb/Br); Manufacturer: Texas Instruments; Alternate Manufacturer: None; Alternate PartNumber: Equivalent; Breakdown Voltage(Min)(V): 11; IEC 61000-4-2 Air-Gap(+/- kV): 15; IEC 61000-4-2 Contact(+/- kV): 8; IO Capacitance(Typ)(pF): 1.5; IO Leakage Current(nA): 1; SubFamily: ESD Solution; USB High Speed: TRUE
U906 U907 = TPS2513DBV: DUAL CHANNEL AUTO DETECT USB CHARGING CONTROLLER, DBV0006A; Alternate Manufacturer: None; Manufacturer: Texas Instruments; SymbolCreator: a0411947; CompType: IC; U/M: EA

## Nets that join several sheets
GND2: PMP10974_BlankSheet (20 pins), PMP10974_TID_Hardware (48 pins)
VOUT: PMP10974_BlankSheet (14 pins), PMP10974_TID_Hardware (28 pins)

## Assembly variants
001: not fitted R917 R919 R920 R921 R922 R923 R924 R925 U902 U903 U910 U911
